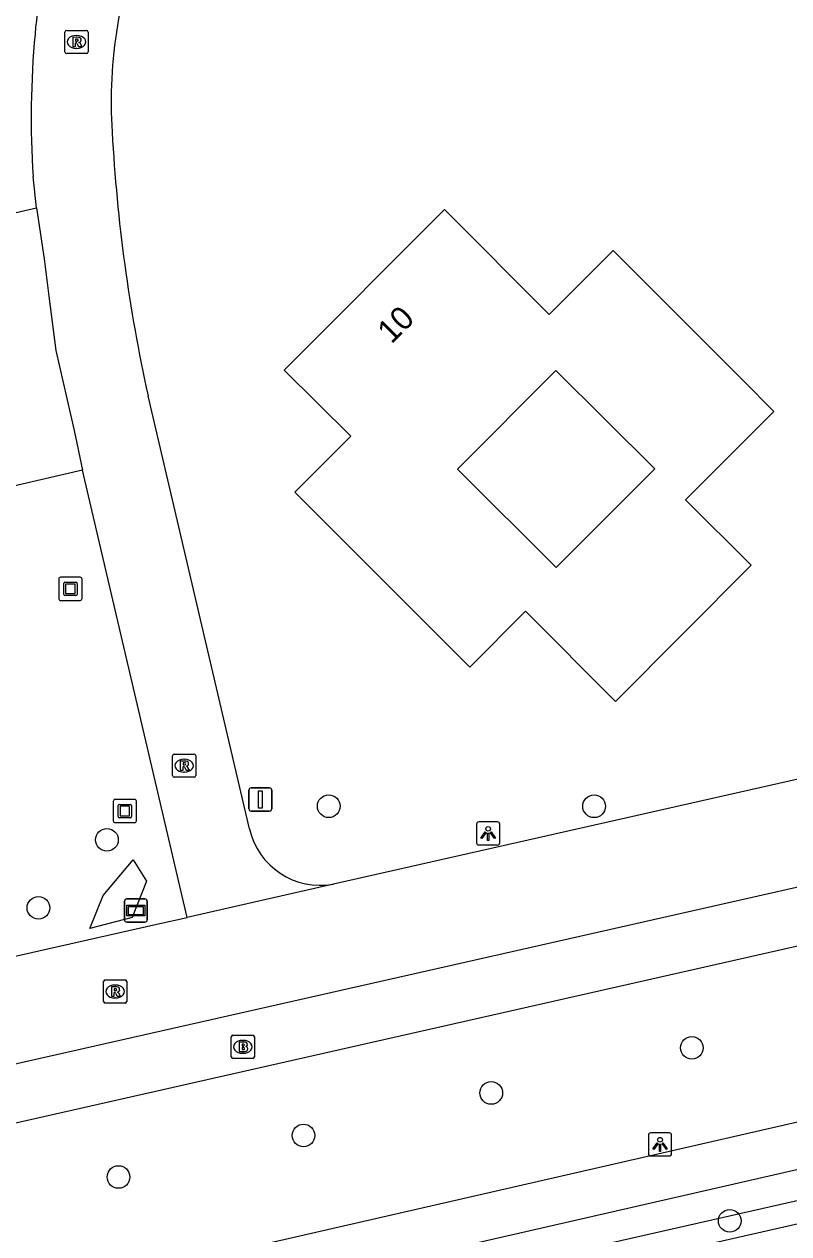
# Model space of a CAD drawing. Extents: x 156664 to 157568, y 383571 to 384421.
# Drawn here: x 156840.7 to 156873.7, y 384078.5 to 384130.7 of the extents above; entities that cross this region are included whole.
import ezdxf

# ---------------------------------------------------------------- set-up
doc = ezdxf.new("R2010")
doc.units = 0
for name, color, linetype in [('IMGEO_Boom', 7, 'Continuous'), ('IMGEO_Brandkraan', 7, 'Continuous'), ('IMGEO_Groenvoorziening', 7, 'Continuous'), ('IMGEO_Haag', 7, 'Continuous'), ('IMGEO_Kunstobject', 7, 'Continuous'), ('IMGEO_Lichtpunt', 7, 'Continuous'), ('IMGEO_Pand', 7, 'Continuous'), ('IMGEO_Pand_nummerreeks', 7, 'Continuous'), ('IMGEO_Parkeervlak_open', 7, 'Continuous'), ('IMGEO_Rijbaan_lokaal_gesloten', 7, 'Continuous'), ('IMGEO_Rijbaan_lokaal_open', 7, 'Continuous'), ('IMGEO_Rioolput', 7, 'Continuous'), ('IMGEO_Straatnaambord', 7, 'Continuous'), ('IMGEO_Verkeersbordpaal', 7, 'Continuous'), ('IMGEO_Voetpad_open', 7, 'Continuous')]:
    doc.layers.add(name, color=color, linetype=linetype)

msp = doc.modelspace()

# ---------------------------------------------------------------- linework, layer by layer
at = {"layer": 'IMGEO_Boom'}
for centre in [(156853.802, 384096.926), (156865.256, 384096.924), (156844.232, 384095.478), (156841.273, 384092.538), (156869.472, 384086.493), (156860.817, 384084.546), (156852.713, 384082.713), (156844.731, 384080.918), (156871.109, 384079.023)]:
    msp.add_circle(centre, 0.489, dxfattribs=at)
at = {"layer": 'IMGEO_Brandkraan'}
for p, q in [((156849.595, 384086.112), (156849.595, 384086.964)), ((156849.67, 384087.038), (156850.522, 384087.038)), ((156850.083, 384086.818), (156850.108, 384086.818)), ((156850.596, 384086.964), (156850.596, 384086.112)), ((156850.106, 384086.258), (156850.081, 384086.258)), ((156850.522, 384086.038), (156849.67, 384086.038))]:
    msp.add_line(p, q, dxfattribs=at)
for points in [[(156849.595, 384086.112), (156849.595, 384086.964)], [(156849.67, 384087.038), (156850.522, 384087.038)], [(156850.596, 384086.964), (156850.596, 384086.112)], [(156849.943, 384086.738), (156849.943, 384086.338), (156850.156, 384086.338)], [(156850.174, 384086.738), (156849.943, 384086.738)], [(156850.122, 384086.657), (156850.068, 384086.657), (156850.068, 384086.581)], [(156850.068, 384086.581), (156850.121, 384086.581)], [(156850.13, 384086.505), (156850.068, 384086.505), (156850.068, 384086.424)], [(156850.068, 384086.424), (156850.13, 384086.424)], [(156850.522, 384086.038), (156849.67, 384086.038)]]:
    msp.add_lwpolyline(points, dxfattribs=at)
for centre, radius, start, end in [((156849.672, 384086.962), 0.0765, 91.552, 178.448), ((156849.672, 384086.962), 0.0765, 91.552, 178.448), ((156850.52, 384086.962), 0.0765, 1.552, 88.448), ((156850.52, 384086.962), 0.0765, 1.552, 88.448), ((156850.123, 384086.619), 0.0379, 267.8285, 90.9355), ((156850.131, 384086.464), 0.0404, 269.8759, 90.5077), ((156850.162, 384086.589), 0.251, 268.6676, 293.5347), ((156850.178, 384086.593), 0.145, 59.4692, 91.5367), ((156850.203, 384086.64), 0.0922, 285.5137, 58.1501), ((156850.208, 384086.448), 0.105, 301.3115, 78.989), ((156849.672, 384086.114), 0.0765, 181.552, 268.448), ((156849.672, 384086.114), 0.0765, 181.552, 268.448), ((156850.52, 384086.114), 0.0765, 271.552, 358.448), ((156850.52, 384086.114), 0.0765, 271.552, 358.448)]:
    msp.add_arc(centre, radius, start, end, dxfattribs=at)
for centre, major_axis, ratio, start_param, end_param in [((156850.082, 384086.538), (-0.387, 0.002), 0.722429, 4.712389, 7.853982), ((156850.107, 384086.538), (-0.39, 0.002), 0.717154, 1.570796, 4.712389)]:
    msp.add_ellipse(centre, major_axis=major_axis, ratio=ratio, start_param=start_param, end_param=end_param, dxfattribs=at)
at = {"layer": 'IMGEO_Groenvoorziening'}
for points in [[(156834.464, 384121.23), (156841.185, 384122.765)], [(156843.173, 384111.435), (156833.179, 384109.127)], [(156845.368, 384094.609), (156845.934, 384093.685), (156845.314, 384092.127), (156843.491, 384091.645), (156844.061, 384093.079), (156845.368, 384094.609)]]:
    msp.add_lwpolyline(points, dxfattribs=at)
at = {"layer": 'IMGEO_Haag'}
msp.add_lwpolyline([(156842.768, 384071.784), (156842.547, 384072.759), (156888.556, 384083.206), (156888.777, 384082.231), (156842.768, 384071.784)], dxfattribs=at)
at = {"layer": 'IMGEO_Kunstobject'}
for p, q in [((156842.155, 384106.727), (156842.155, 384105.886)), ((156842.155, 384106.727), (156842.155, 384105.886)), ((156843.071, 384106.811), (156842.23, 384106.811)), ((156843.071, 384106.811), (156842.23, 384106.811)), ((156843.155, 384105.895), (156843.155, 384106.736)), ((156843.155, 384105.895), (156843.155, 384106.736)), ((156842.369, 384106.075), (156842.369, 384106.549)), ((156842.419, 384106.599), (156842.893, 384106.599)), ((156842.449, 384106.499), (156842.449, 384106.125)), ((156842.843, 384106.519), (156842.469, 384106.519)), ((156842.469, 384106.105), (156842.843, 384106.105)), ((156842.863, 384106.125), (156842.863, 384106.499)), ((156842.943, 384106.549), (156842.943, 384106.075)), ((156842.239, 384105.811), (156843.08, 384105.811)), ((156842.239, 384105.811), (156843.08, 384105.811)), ((156842.893, 384106.025), (156842.419, 384106.025)), ((156844.503, 384097.134), (156844.503, 384096.293)), ((156844.503, 384097.134), (156844.503, 384096.293)), ((156845.419, 384097.218), (156844.578, 384097.218)), ((156845.419, 384097.218), (156844.578, 384097.218)), ((156844.717, 384096.482), (156844.717, 384096.956)), ((156844.767, 384097.006), (156845.241, 384097.006)), ((156844.797, 384096.906), (156844.797, 384096.532)), ((156845.191, 384096.926), (156844.817, 384096.926)), ((156845.211, 384096.532), (156845.211, 384096.906)), ((156845.291, 384096.956), (156845.291, 384096.482)), ((156845.503, 384096.302), (156845.503, 384097.143)), ((156845.503, 384096.302), (156845.503, 384097.143)), ((156844.587, 384096.218), (156845.428, 384096.218)), ((156844.587, 384096.218), (156845.428, 384096.218)), ((156845.241, 384096.432), (156844.767, 384096.432)), ((156844.817, 384096.512), (156845.191, 384096.512))]:
    msp.add_line(p, q, dxfattribs=at)
for centre, radius, start, end in [((156842.233, 384106.733), 0.0779, 92.4484, 184.2845), ((156842.233, 384106.733), 0.0779, 92.4484, 184.2845), ((156843.077, 384106.733), 0.0779, 2.4484, 94.2845), ((156843.077, 384106.733), 0.0779, 2.4484, 94.2845), ((156842.419, 384106.549), 0.05, 90, 180), ((156842.469, 384106.499), 0.02, 90, 180), ((156842.469, 384106.125), 0.02, 180, 270), ((156842.843, 384106.499), 0.02, 360, 90), ((156842.843, 384106.125), 0.02, 270, 0), ((156842.893, 384106.549), 0.05, 360, 90), ((156842.233, 384105.889), 0.0779, 182.4484, 274.2845), ((156842.233, 384105.889), 0.0779, 182.4484, 274.2845), ((156842.419, 384106.075), 0.05, 180, 270), ((156842.893, 384106.075), 0.05, 270, 0), ((156843.077, 384105.889), 0.0779, 272.4484, 4.2845), ((156843.077, 384105.889), 0.0779, 272.4484, 4.2845), ((156844.581, 384097.14), 0.0779, 92.4484, 184.2845), ((156844.581, 384097.14), 0.0779, 92.4484, 184.2845), ((156844.767, 384096.956), 0.05, 90, 180), ((156844.817, 384096.906), 0.02, 90, 180), ((156845.191, 384096.906), 0.02, 360, 90), ((156845.241, 384096.956), 0.05, 360, 90), ((156845.425, 384097.14), 0.0779, 2.4484, 94.2845), ((156845.425, 384097.14), 0.0779, 2.4484, 94.2845), ((156844.581, 384096.296), 0.0779, 182.4484, 274.2845), ((156844.581, 384096.296), 0.0779, 182.4484, 274.2845), ((156844.767, 384096.482), 0.05, 180, 270), ((156844.817, 384096.532), 0.02, 180, 270), ((156845.191, 384096.532), 0.02, 270, 0), ((156845.241, 384096.482), 0.05, 270, 0), ((156845.425, 384096.296), 0.0779, 272.4484, 4.2845), ((156845.425, 384096.296), 0.0779, 272.4484, 4.2845)]:
    msp.add_arc(centre, radius, start, end, dxfattribs=at)
at = {"layer": 'IMGEO_Lichtpunt'}
for p, q in [((156861.087, 384096.249), (156860.279, 384096.249)), ((156861.087, 384096.249), (156860.279, 384096.249)), ((156860.185, 384096.154), (156860.185, 384095.347)), ((156860.185, 384096.154), (156860.185, 384095.347)), ((156861.181, 384095.347), (156861.181, 384096.154)), ((156861.181, 384095.347), (156861.181, 384096.154)), ((156860.279, 384095.253), (156861.087, 384095.253)), ((156860.279, 384095.253), (156861.087, 384095.253)), ((156867.604, 384082.727), (156867.604, 384081.92)), ((156867.604, 384082.727), (156867.604, 384081.92)), ((156868.506, 384082.822), (156867.698, 384082.822)), ((156868.506, 384082.822), (156867.698, 384082.822)), ((156868.6, 384081.92), (156868.6, 384082.727)), ((156868.6, 384081.92), (156868.6, 384082.727)), ((156867.698, 384081.826), (156868.506, 384081.826)), ((156867.698, 384081.826), (156868.506, 384081.826))]:
    msp.add_line(p, q, dxfattribs=at)
for points in [[(156860.559, 384095.818), (156860.598, 384095.79), (156860.41, 384095.528), (156860.372, 384095.555), (156860.559, 384095.818)], [(156860.661, 384095.77), (156860.708, 384095.77), (156860.708, 384095.448), (156860.661, 384095.448), (156860.661, 384095.77)], [(156860.771, 384095.79), (156860.809, 384095.817), (156860.996, 384095.555), (156860.957, 384095.527), (156860.771, 384095.79)], [(156867.978, 384082.391), (156868.017, 384082.363), (156867.829, 384082.101), (156867.791, 384082.128), (156867.978, 384082.391)], [(156868.08, 384082.343), (156868.127, 384082.343), (156868.127, 384082.021), (156868.08, 384082.021), (156868.08, 384082.343)], [(156868.19, 384082.363), (156868.228, 384082.39), (156868.415, 384082.128), (156868.376, 384082.1), (156868.19, 384082.363)]]:
    msp.add_lwpolyline(points, dxfattribs=at)
for centre in [(156860.684, 384095.952), (156868.103, 384082.525)]:
    msp.add_circle(centre, 0.0994, dxfattribs=at)
for centre, start, end in [((156860.279, 384096.154), 90, 180), ((156860.279, 384096.154), 90, 180), ((156861.087, 384096.154), 0, 90), ((156861.087, 384096.154), 0, 90), ((156860.279, 384095.347), 180, 270), ((156860.279, 384095.347), 180, 270), ((156861.087, 384095.347), 270, 0), ((156861.087, 384095.347), 270, 360), ((156867.698, 384082.727), 90, 180), ((156867.698, 384082.727), 90, 180), ((156868.506, 384082.727), 0, 90), ((156868.506, 384082.727), 0, 90), ((156867.698, 384081.92), 180, 270), ((156867.698, 384081.92), 180, 270), ((156868.506, 384081.92), 270, 0), ((156868.506, 384081.92), 270, 360)]:
    msp.add_arc(centre, 0.0946, start, end, dxfattribs=at)
at = {"layer": 'IMGEO_Pand'}
for points in [[(156866.078, 384120.92), (156863.322, 384118.162), (156858.804, 384122.686), (156851.877, 384115.755), (156854.756, 384112.91), (156852.337, 384110.494), (156859.886, 384102.937), (156862.299, 384105.343), (156866.185, 384101.447), (156872.036, 384107.331), (156869.207, 384110.156), (156873.019, 384113.965), (156871.671, 384115.318), (156866.078, 384120.92)], [(156863.623, 384107.234), (156867.871, 384111.489), (156863.61, 384115.742), (156859.362, 384111.487), (156863.623, 384107.234)]]:
    msp.add_lwpolyline(points, dxfattribs=at)
at = {"layer": 'IMGEO_Parkeervlak_open'}
msp.add_lwpolyline([(156886.622, 384093.732), (156825.408, 384079.879), (156824.856, 384082.318)], dxfattribs=at)
at = {"layer": 'IMGEO_Rijbaan_lokaal_gesloten'}
for points in [[(156841.185, 384122.765), (156841.045, 384124.11)], [(156841.185, 384122.765), (156841.521, 384120.565), (156841.723, 384118.955), (156842.028, 384116.611), (156842.81, 384113.152), (156843.173, 384111.435)], [(156850.379, 384095.956), (156846.003, 384114.65)], [(156847.686, 384092.128), (156843.173, 384111.435)], [(156854.008, 384093.566), (156847.686, 384092.128)]]:
    msp.add_lwpolyline(points, dxfattribs=at)
for centre, radius, start, end in [((156860.109, 384128.64), 19.052, 146.7202, 175.1027), ((156864.498, 384127.333), 20.087, 157.3732, 183.7104), ((156880.335, 384126.672), 39.373, 174.7621, 183.7302), ((156915.828, 384129.955), 71.482, 183.14515, 192.36317), ((156853.436, 384096.647), 3.134, 192.7442, 280.5193)]:
    msp.add_arc(centre, radius, start, end, dxfattribs=at)
at = {"layer": 'IMGEO_Rijbaan_lokaal_open'}
for points in [[(156914.342, 384107.209), (156854.008, 384093.566)], [(156824.856, 384082.318), (156884.236, 384095.756)], [(156814.968, 384084.702), (156816.621, 384085.092), (156819.069, 384085.654), (156846.389, 384091.834), (156847.686, 384092.128)]]:
    msp.add_lwpolyline(points, dxfattribs=at)
at = {"layer": 'IMGEO_Rioolput'}
for p, q in [((156842.419, 384129.501), (156842.419, 384130.353)), ((156842.494, 384130.427), (156843.346, 384130.427)), ((156842.907, 384130.207), (156842.932, 384130.207)), ((156843.42, 384130.353), (156843.42, 384129.501)), ((156842.93, 384129.647), (156842.905, 384129.647)), ((156843.346, 384129.427), (156842.494, 384129.427)), ((156847.061, 384098.251), (156847.061, 384099.103)), ((156847.136, 384099.177), (156847.988, 384099.177)), ((156847.549, 384098.957), (156847.574, 384098.957)), ((156848.062, 384099.103), (156848.062, 384098.251)), ((156847.572, 384098.397), (156847.547, 384098.397)), ((156847.988, 384098.177), (156847.136, 384098.177)), ((156844.159, 384089.427), (156845.011, 384089.427)), ((156844.084, 384088.501), (156844.084, 384089.353)), ((156844.572, 384089.207), (156844.597, 384089.207)), ((156845.085, 384089.353), (156845.085, 384088.501)), ((156845.011, 384088.427), (156844.159, 384088.427)), ((156844.595, 384088.647), (156844.57, 384088.647))]:
    msp.add_line(p, q, dxfattribs=at)
for points in [[(156842.419, 384129.501), (156842.419, 384130.353)], [(156842.494, 384130.427), (156843.346, 384130.427)], [(156843.42, 384130.353), (156843.42, 384129.501)], [(156843.008, 384130.125), (156842.756, 384130.127), (156842.756, 384129.727)], [(156842.756, 384129.727), (156842.88, 384129.727), (156842.88, 384129.889), (156842.891, 384129.889)], [(156842.934, 384130.046), (156842.88, 384130.046), (156842.88, 384129.965)], [(156842.88, 384129.965), (156842.932, 384129.965)], [(156842.938, 384129.86), (156843.009, 384129.727), (156843.149, 384129.727), (156843.084, 384129.853)], [(156843.346, 384129.427), (156842.494, 384129.427)], [(156847.061, 384098.251), (156847.061, 384099.103)], [(156847.136, 384099.177), (156847.988, 384099.177)], [(156847.65, 384098.875), (156847.398, 384098.877), (156847.398, 384098.477)], [(156847.576, 384098.796), (156847.522, 384098.796), (156847.522, 384098.715)], [(156848.062, 384099.103), (156848.062, 384098.251)], [(156847.398, 384098.477), (156847.522, 384098.477), (156847.522, 384098.639), (156847.533, 384098.639)], [(156847.522, 384098.715), (156847.574, 384098.715)], [(156847.58, 384098.61), (156847.651, 384098.477), (156847.791, 384098.477), (156847.726, 384098.603)], [(156847.988, 384098.177), (156847.136, 384098.177)], [(156844.159, 384089.427), (156845.011, 384089.427)], [(156844.084, 384088.501), (156844.084, 384089.353)], [(156844.673, 384089.125), (156844.421, 384089.127), (156844.421, 384088.727)], [(156844.421, 384088.727), (156844.545, 384088.727), (156844.545, 384088.889), (156844.556, 384088.889)], [(156844.599, 384089.046), (156844.545, 384089.046), (156844.545, 384088.965)], [(156844.545, 384088.965), (156844.597, 384088.965)], [(156845.085, 384089.353), (156845.085, 384088.501)], [(156845.011, 384088.427), (156844.159, 384088.427)], [(156844.603, 384088.86), (156844.674, 384088.727), (156844.814, 384088.727), (156844.749, 384088.853)]]:
    msp.add_lwpolyline(points, dxfattribs=at)
for centre, radius, start, end in [((156842.496, 384130.351), 0.0765, 91.552, 178.448), ((156842.496, 384130.351), 0.0765, 91.552, 178.448), ((156843.344, 384130.351), 0.0765, 1.552, 88.448), ((156843.344, 384130.351), 0.0765, 1.552, 88.448), ((156842.89, 384129.836), 0.0533, 26.0293, 88.6989), ((156842.916, 384130.154), 0.19, 274.7715, 282.9687), ((156842.94, 384129.95), 0.0964, 77.0061, 93.1865), ((156842.954, 384130.007), 0.0378, 276.6634, 79.6772), ((156843.007, 384130.015), 0.109, 350.3612, 89.416), ((156843.005, 384130.015), 0.112, 277.5842, 350.9817), ((156842.989, 384129.8), 0.108, 29.5134, 73.7905), ((156842.496, 384129.503), 0.0765, 181.552, 268.448), ((156842.496, 384129.503), 0.0765, 181.552, 268.448), ((156843.344, 384129.503), 0.0765, 271.552, 358.448), ((156843.344, 384129.503), 0.0765, 271.552, 358.448), ((156847.138, 384099.101), 0.0765, 91.552, 178.448), ((156847.138, 384099.101), 0.0765, 91.552, 178.448), ((156847.582, 384098.7), 0.0964, 77.0061, 93.1865), ((156847.596, 384098.757), 0.0378, 276.6634, 79.6772), ((156847.649, 384098.765), 0.109, 350.3612, 89.416), ((156847.986, 384099.101), 0.0765, 1.552, 88.448), ((156847.986, 384099.101), 0.0765, 1.552, 88.448), ((156847.532, 384098.586), 0.0533, 26.0293, 88.6989), ((156847.558, 384098.904), 0.19, 274.7715, 282.9687), ((156847.647, 384098.765), 0.112, 277.5842, 350.9817), ((156847.631, 384098.55), 0.108, 29.5134, 73.7905), ((156847.138, 384098.253), 0.0765, 181.552, 268.448), ((156847.138, 384098.253), 0.0765, 181.552, 268.448), ((156847.986, 384098.253), 0.0765, 271.552, 358.448), ((156847.986, 384098.253), 0.0765, 271.552, 358.448), ((156844.161, 384089.351), 0.0765, 91.552, 178.448), ((156844.161, 384089.351), 0.0765, 91.552, 178.448), ((156845.009, 384089.351), 0.0765, 1.552, 88.448), ((156845.009, 384089.351), 0.0765, 1.552, 88.448), ((156844.555, 384088.836), 0.0533, 26.0293, 88.6989), ((156844.581, 384089.154), 0.19, 274.7715, 282.9687), ((156844.605, 384088.95), 0.0964, 77.0061, 93.1865), ((156844.619, 384089.007), 0.0378, 276.6634, 79.6772), ((156844.672, 384089.015), 0.109, 350.3612, 89.416), ((156844.67, 384089.015), 0.112, 277.5842, 350.9817), ((156844.654, 384088.8), 0.108, 29.5134, 73.7905), ((156844.161, 384088.503), 0.0765, 181.552, 268.448), ((156844.161, 384088.503), 0.0765, 181.552, 268.448), ((156845.009, 384088.503), 0.0765, 271.552, 358.448), ((156845.009, 384088.503), 0.0765, 271.552, 358.448)]:
    msp.add_arc(centre, radius, start, end, dxfattribs=at)
for centre, major_axis, ratio, start_param, end_param in [((156842.906, 384129.927), (-0.387, 0.002), 0.722429, 4.712389, 7.853982), ((156842.931, 384129.927), (-0.39, 0.002), 0.717154, 1.570796, 4.712389), ((156847.548, 384098.677), (-0.387, 0.002), 0.722429, 4.712389, 7.853982), ((156847.573, 384098.677), (-0.39, 0.002), 0.717154, 1.570796, 4.712389), ((156844.571, 384088.927), (-0.387, 0.002), 0.722429, 4.712389, 7.853982), ((156844.596, 384088.927), (-0.39, 0.002), 0.717154, 1.570796, 4.712389)]:
    msp.add_ellipse(centre, major_axis=major_axis, ratio=ratio, start_param=start_param, end_param=end_param, dxfattribs=at)
at = {"layer": 'IMGEO_Straatnaambord'}
for p, q in [((156844.983, 384092.022), (156844.983, 384092.822)), ((156844.983, 384092.822), (156844.983, 384092.022)), ((156845.083, 384092.922), (156845.873, 384092.922)), ((156845.873, 384092.922), (156845.083, 384092.922)), ((156845.973, 384092.822), (156845.973, 384092.022)), ((156845.973, 384092.022), (156845.973, 384092.822)), ((156845.873, 384091.922), (156845.083, 384091.922)), ((156845.083, 384091.922), (156845.873, 384091.922))]:
    msp.add_line(p, q, dxfattribs=at)
for points in [[(156845.084, 384092.654), (156845.872, 384092.654), (156845.872, 384092.19), (156845.084, 384092.19), (156845.084, 384092.654)], [(156845.149, 384092.589), (156845.149, 384092.255), (156845.807, 384092.255), (156845.807, 384092.589), (156845.149, 384092.589)]]:
    msp.add_lwpolyline(points, dxfattribs=at)
for centre, start, end in [((156845.083, 384092.822), 90, 180), ((156845.083, 384092.822), 90, 180), ((156845.873, 384092.822), 0, 90), ((156845.873, 384092.822), 360, 90), ((156845.083, 384092.022), 180, 270), ((156845.083, 384092.022), 180, 270), ((156845.873, 384092.022), 270, 0), ((156845.873, 384092.022), 270, 0)]:
    msp.add_arc(centre, 0.1, start, end, dxfattribs=at)
at = {"layer": 'IMGEO_Verkeersbordpaal'}
for p, q in [((156850.355, 384096.82), (156850.355, 384097.62)), ((156850.355, 384097.62), (156850.355, 384096.82)), ((156850.455, 384097.72), (156851.245, 384097.72)), ((156851.245, 384097.72), (156850.455, 384097.72)), ((156851.345, 384097.62), (156851.345, 384096.82)), ((156851.345, 384096.82), (156851.345, 384097.62)), ((156851.245, 384096.72), (156850.455, 384096.72)), ((156850.455, 384096.72), (156851.245, 384096.72))]:
    msp.add_line(p, q, dxfattribs=at)
msp.add_lwpolyline([(156850.775, 384097.595), (156850.925, 384097.595), (156850.925, 384096.845), (156850.775, 384096.845), (156850.775, 384097.595)], dxfattribs=at)
for centre, start, end in [((156850.455, 384097.62), 90, 180), ((156850.455, 384097.62), 90, 180), ((156851.245, 384097.62), 0, 90), ((156851.245, 384097.62), 360, 90), ((156850.455, 384096.82), 180, 270), ((156850.455, 384096.82), 180, 270), ((156851.245, 384096.82), 270, 0), ((156851.245, 384096.82), 270, 0)]:
    msp.add_arc(centre, 0.1, start, end, dxfattribs=at)
at = {"layer": 'IMGEO_Voetpad_open'}
for points in [[(156888.427, 384086.586), (156811.028, 384068.852)], [(156888.906, 384084.645), (156834.367, 384072.163)]]:
    msp.add_lwpolyline(points, dxfattribs=at)

# ---------------------------------------------------------------- texts
at = {"layer": 'IMGEO_Pand_nummerreeks'}
msp.add_text('10', height=1, rotation=44.8168, dxfattribs=at).set_placement((156856.51, 384116.859))

doc.saveas('drawing.dxf')
